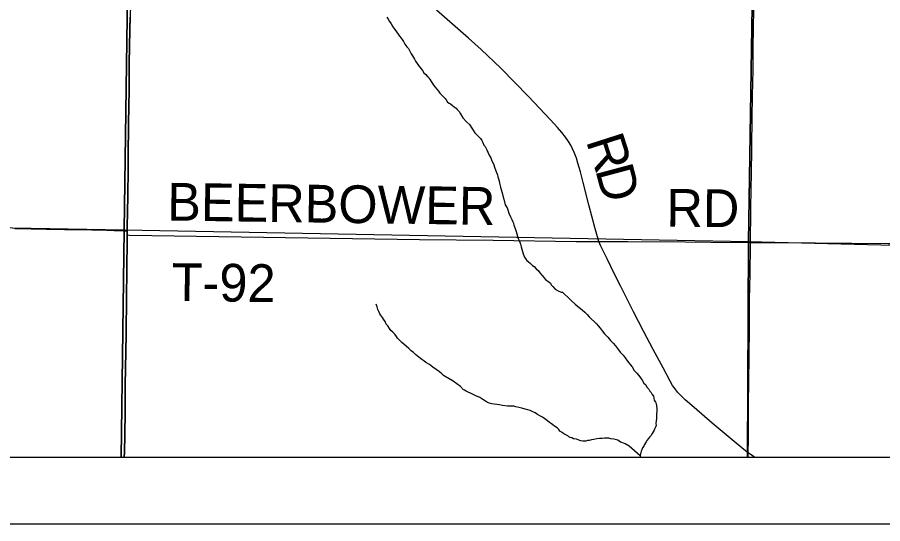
# Model space of a CAD drawing. Extents: x 0 to 34, y 0 to 22.
# Drawn here: x 6.454 to 7.757, y 14 to 14.762 of the extents above; entities that cross this region are included whole.
import ezdxf

# ---------------------------------------------------------------- set-up
doc = ezdxf.new("R2010")
doc.units = 0
for name, color, linetype in [('GM_X_County_Road', 7, 'Continuous'), ('GM_X_County_Road_Text', 7, 'Continuous'), ('GM_X_County_Text', 7, 'Continuous'), ('GM_X_Minor_River', 7, 'Continuous'), ('GM_X_Rail_Line_Text', 7, 'Continuous'), ('GM_X_Section', 7, 'Continuous'), ('GM_X_Township_Road', 7, 'Continuous'), ('GM_X_Township_Road_Text', 7, 'Continuous'), ('GM_X_US_Route', 7, 'Continuous'), ('SH_Cut_Line', 7, 'Continuous'), ('SH_Data', 7, 'Continuous')]:
    doc.layers.add(name, color=color, linetype=linetype)

msp = doc.modelspace()

# ---------------------------------------------------------------- linework, layer by layer
at = {"layer": 'GM_X_County_Road'}
for points in [[(7.3294, 14.425), (7.3236, 14.4459), (7.3145, 14.4802), (7.3057, 14.5135), (7.3017, 14.5298), (7.2981, 14.543), (7.2957, 14.5506), (7.2928, 14.5581), (7.29, 14.5643), (7.2872, 14.5698), (7.2837, 14.5756), (7.2792, 14.5822), (7.2739, 14.5891), (7.2675, 14.5966), (7.2569, 14.608), (7.2234, 14.6431), (7.182, 14.686), (7.1522, 14.7142), (7.1332, 14.7311), (7.0851, 14.7734)], [(7.5546, 14.1065), (7.5502, 14.1097), (7.5362, 14.1211), (7.5, 14.1516), (7.4731, 14.1747), (7.4596, 14.1866), (7.4533, 14.1926), (7.4482, 14.1982), (7.4442, 14.203), (7.4406, 14.2082), (7.4368, 14.2147), (7.4263, 14.2345), (7.4111, 14.2623), (7.3968, 14.2899), (7.3817, 14.3192), (7.3627, 14.357), (7.3525, 14.3769), (7.3424, 14.3976), (7.3326, 14.4177), (7.3294, 14.425)], [(7.564, 14.1), (7.5624, 14.101), (7.5546, 14.1065)]]:
    msp.add_lwpolyline(points, dxfattribs=at)
at = {"layer": 'GM_X_County_Text'}
for points in [[(2.1, 14.1), (6.615, 14.1), (6.6152, 14.1077), (6.6156, 14.1338), (6.6161, 14.1686), (6.6162, 14.1885), (6.6165, 14.2084), (6.6171, 14.2594), (6.6176, 14.2849), (6.6183, 14.3433), (6.6186, 14.3794), (6.6193, 14.4303), (6.6193, 14.4352), (6.6194, 14.4415), (6.6194, 14.4465), (6.6202, 14.4931), (6.6207, 14.5342), (6.621, 14.5565), (6.6216, 14.5988), (6.6221, 14.6324), (6.6222, 14.6492), (6.6222, 14.6647), (6.6226, 14.6952), (6.6231, 14.7176), (6.6236, 14.7449), (6.6241, 14.7629)], [(6.6241, 14.7629), (6.6236, 14.7449), (6.6231, 14.7176), (6.6226, 14.6952), (6.6222, 14.6647), (6.6222, 14.6492), (6.6221, 14.6324), (6.6216, 14.5988), (6.621, 14.5565), (6.6207, 14.5342), (6.6202, 14.4931), (6.6194, 14.4465), (6.6194, 14.4415), (6.6193, 14.4352), (6.6193, 14.4303), (6.6186, 14.3794), (6.6183, 14.3433), (6.6176, 14.2849), (6.6171, 14.2594), (6.6165, 14.2084), (6.6162, 14.1885), (6.6161, 14.1686), (6.6156, 14.1338), (6.6152, 14.1077), (6.615, 14.1), (8.9, 14.1)]]:
    msp.add_lwpolyline(points, dxfattribs=at)
at = {"layer": 'GM_X_Minor_River'}
for points in [[(7.0104, 14.7628), (7.0122, 14.7597), (7.0144, 14.7563), (7.0166, 14.7528), (7.0192, 14.7482), (7.0225, 14.7439), (7.0251, 14.7404), (7.0273, 14.7373), (7.0295, 14.7342), (7.0317, 14.7312), (7.0335, 14.7288), (7.0354, 14.7261), (7.0375, 14.7219), (7.0405, 14.718), (7.0427, 14.7153), (7.0438, 14.7134), (7.0456, 14.7107), (7.0471, 14.7076), (7.0489, 14.7045), (7.0507, 14.7018), (7.0522, 14.6995), (7.0537, 14.6964), (7.0558, 14.693), (7.0581, 14.6899), (7.0599, 14.6872), (7.0621, 14.6848), (7.064, 14.6825), (7.0661, 14.6786), (7.0691, 14.6763), (7.071, 14.674), (7.0728, 14.6724), (7.0743, 14.6705), (7.0754, 14.6682), (7.0769, 14.6659), (7.0791, 14.6628), (7.0805, 14.6601), (7.0879, 14.6511), (7.0901, 14.6484), (7.0931, 14.6453), (7.0949, 14.6434), (7.0979, 14.6403), (7.0997, 14.6383), (7.1019, 14.6349), (7.1042, 14.6333), (7.106, 14.6321), (7.1094, 14.6297), (7.1116, 14.6278), (7.1146, 14.6254), (7.1161, 14.6235), (7.1191, 14.6204), (7.1213, 14.6169), (7.1245, 14.6111), (7.1301, 14.6049), (7.1349, 14.601), (7.1382, 14.5956), (7.1426, 14.5883), (7.1485, 14.5828), (7.1511, 14.5801), (7.1533, 14.577), (7.1548, 14.5739), (7.1566, 14.5697), (7.1584, 14.5678), (7.1599, 14.5651), (7.161, 14.5628), (7.1624, 14.5593), (7.1642, 14.5547), (7.1668, 14.5508), (7.1686, 14.5462), (7.1707, 14.5416)], [(7.1707, 14.5416), (7.1729, 14.5351), (7.1754, 14.5286), (7.1768, 14.5255), (7.1775, 14.5225), (7.1782, 14.5194), (7.1792, 14.516), (7.1799, 14.5129), (7.1817, 14.5068), (7.1824, 14.503), (7.1838, 14.4984), (7.1848, 14.4934), (7.1866, 14.4884), (7.1887, 14.48), (7.1916, 14.4758), (7.1927, 14.4727), (7.1941, 14.4677), (7.1966, 14.462), (7.1984, 14.4581), (7.1995, 14.4554), (7.2009, 14.4527), (7.2016, 14.4493), (7.2034, 14.4443), (7.2048, 14.4401), (7.2062, 14.4363), (7.2083, 14.4294), (7.2098, 14.4263), (7.2105, 14.424), (7.2116, 14.4209), (7.2126, 14.4171), (7.2137, 14.4133), (7.2147, 14.4099), (7.2158, 14.4064), (7.2165, 14.4037), (7.2176, 14.4014), (7.2198, 14.3983), (7.2212, 14.3964), (7.2231, 14.3948), (7.2264, 14.3917), (7.2298, 14.389), (7.232, 14.3874), (7.2354, 14.3839), (7.238, 14.3812), (7.2409, 14.3777), (7.2442, 14.3738), (7.2494, 14.3676), (7.2546, 14.3637), (7.2569, 14.3621), (7.2579, 14.3594), (7.2605, 14.3571), (7.2639, 14.3532), (7.2684, 14.3504), (7.2729, 14.3488), (7.2748, 14.3484), (7.2781, 14.3449), (7.2826, 14.341), (7.2881, 14.3359), (7.2941, 14.3304), (7.2997, 14.3254), (7.3045, 14.3222), (7.3082, 14.3183), (7.312, 14.3152), (7.3149, 14.3117), (7.326, 14.3008), (7.3286, 14.2977), (7.3316, 14.2942), (7.3345, 14.2903), (7.3382, 14.286), (7.343, 14.2806), (7.3471, 14.2756), (7.3512, 14.2717), (7.3545, 14.2678), (7.3578, 14.2639), (7.3615, 14.2585), (7.3659, 14.2538), (7.3693, 14.2496), (7.3726, 14.2446), (7.3766, 14.2395), (7.3799, 14.236), (7.3825, 14.2306), (7.3869, 14.2267), (7.3895, 14.2233), (7.3921, 14.2194), (7.3947, 14.2159), (7.3972, 14.2117), (7.4002, 14.2089), (7.402, 14.2055), (7.4046, 14.2024), (7.4064, 14.1997), (7.4083, 14.1973), (7.4097, 14.1943), (7.4116, 14.1919), (7.4129, 14.1862), (7.4148, 14.1828), (7.4158, 14.1808), (7.4168, 14.1736), (7.4168, 14.1736), (7.4165, 14.161), (7.4161, 14.1584), (7.4156, 14.155), (7.4155, 14.1508)], [(7.0249, 14.2818), (7.0224, 14.2853), (7.0194, 14.2884), (7.0164, 14.2911), (7.0142, 14.2938), (7.0117, 14.2981), (7.0091, 14.3004), (7.0076, 14.3042), (7.0054, 14.3077), (7.0036, 14.3104), (7.0021, 14.3123), (7.001, 14.3143), (6.9999, 14.3162), (6.9985, 14.3197), (6.9967, 14.3227), (6.996, 14.3266), (6.9943, 14.3305)], [(7.3916, 14.102), (7.3752, 14.1168), (7.3693, 14.1204), (7.364, 14.1224), (7.3621, 14.1225), (7.358, 14.1256), (7.352, 14.1273), (7.3474, 14.1277), (7.3444, 14.1286), (7.341, 14.1287), (7.3379, 14.1287), (7.3345, 14.1284), (7.3307, 14.1285), (7.3265, 14.1279), (7.322, 14.1268), (7.3185, 14.1262), (7.3151, 14.1255), (7.3124, 14.1252), (7.3098, 14.1245), (7.3075, 14.1245), (7.3056, 14.1242), (7.3025, 14.1246), (7.3007, 14.1254), (7.2984, 14.1263), (7.2958, 14.1271), (7.2916, 14.1279), (7.289, 14.1291), (7.2863, 14.13), (7.2845, 14.1308), (7.2826, 14.1323), (7.2796, 14.1339), (7.277, 14.1355), (7.2744, 14.1371), (7.2706, 14.1395), (7.2692, 14.1418), (7.2666, 14.1445), (7.2628, 14.1469), (7.2602, 14.1488), (7.258, 14.1504), (7.2554, 14.1524), (7.252, 14.1551), (7.2483, 14.1579), (7.2445, 14.1602), (7.2408, 14.1626), (7.2374, 14.1646), (7.2337, 14.167), (7.2299, 14.1686), (7.2262, 14.1702), (7.2224, 14.1714), (7.2186, 14.1726), (7.2137, 14.1739), (7.2092, 14.1751), (7.2047, 14.176), (7.2013, 14.1768), (7.199, 14.1769), (7.1971, 14.1769), (7.1922, 14.1771), (7.1846, 14.178), (7.1801, 14.1789), (7.1759, 14.1794), (7.1717, 14.1798), (7.1683, 14.1807), (7.1649, 14.1815), (7.1619, 14.1827), (7.1589, 14.1847), (7.1548, 14.1871), (7.1503, 14.1899), (7.1443, 14.1923), (7.1402, 14.1943), (7.1361, 14.1963), (7.1327, 14.1979), (7.1297, 14.1995), (7.1274, 14.201), (7.1255, 14.2015), (7.1211, 14.2065), (7.1155, 14.2108), (7.1103, 14.2144), (7.0983, 14.2215), (7.0957, 14.2231), (7.0931, 14.2254), (7.0897, 14.2285), (7.0845, 14.2321), (7.0797, 14.2356), (7.0744, 14.2399), (7.0692, 14.2427), (7.0662, 14.2451), (7.0632, 14.247), (7.061, 14.2486), (7.0587, 14.2506), (7.0561, 14.2525), (7.0535, 14.2549), (7.0506, 14.2576), (7.0472, 14.2603), (7.0435, 14.2639), (7.0398, 14.2666), (7.0361, 14.2701), (7.0331, 14.2728), (7.0305, 14.2752), (7.0282, 14.2771), (7.0264, 14.2795), (7.0249, 14.2818)], [(7.4155, 14.1508), (7.4158, 14.1478), (7.4146, 14.1451), (7.4134, 14.1425), (7.4126, 14.1406), (7.4114, 14.1384), (7.4099, 14.1357), (7.4079, 14.1324), (7.4056, 14.1305), (7.4044, 14.1283), (7.402, 14.1253), (7.4008, 14.1234), (7.3997, 14.1216), (7.3985, 14.1193), (7.3973, 14.1167), (7.3953, 14.1141), (7.3941, 14.1114), (7.3933, 14.1092), (7.3921, 14.1054), (7.3916, 14.102), (7.3916, 14.1)]]:
    msp.add_lwpolyline(points, dxfattribs=at)
at = {"layer": 'GM_X_Rail_Line_Text'}
for points in [[(5.6017, 14.1), (6.6103, 14.1), (6.615, 14.4419), (5.6049, 14.4601)], [(6.6103, 14.1), (7.5533, 14.1), (7.5551, 14.4246), (6.615, 14.4419)], [(7.5533, 14.1), (8.5673, 14.1), (8.5711, 14.3987), (7.5551, 14.4246)]]:
    msp.add_lwpolyline(points, close=True, dxfattribs=at)
at = {"layer": 'GM_X_Section'}
for points in [[(5.6179, 15.4598), (6.6291, 15.4393), (6.615, 14.4419), (5.6049, 14.4601)], [(6.6291, 15.4393), (7.5704, 15.4246), (7.5551, 14.4246), (6.615, 14.4419)], [(7.5704, 15.4246), (8.5798, 15.3924), (8.5711, 14.3987), (7.5551, 14.4246)]]:
    msp.add_lwpolyline(points, close=True, dxfattribs=at)
at = {"layer": 'GM_X_Township_Road'}
msp.add_line((6.6196, 14.4347), (6.6196, 14.4409), dxfattribs=at)
for points in [[(6.6196, 14.4409), (6.6197, 14.4459), (6.6204, 14.4926), (6.6209, 14.5336), (6.6213, 14.556), (6.6218, 14.5983), (6.6223, 14.6318), (6.6224, 14.6486), (6.6225, 14.6642), (6.6228, 14.6946), (6.6233, 14.717), (6.6239, 14.7444), (6.6243, 14.7624), (6.6248, 14.7829)], [(6.45, 14.4447), (6.4749, 14.4441), (6.4979, 14.4437), (6.5252, 14.4432), (6.5663, 14.4426), (6.5881, 14.442), (6.5996, 14.4417), (6.6074, 14.4414), (6.6155, 14.441), (6.6196, 14.4409)], [(6.6153, 14.1), (6.6154, 14.1071), (6.6158, 14.1332), (6.6164, 14.168), (6.6164, 14.1879), (6.6167, 14.2078), (6.6174, 14.2588), (6.6178, 14.2843), (6.6185, 14.3427), (6.6189, 14.3788), (6.6195, 14.4298), (6.6196, 14.4347)], [(6.6196, 14.4347), (6.6229, 14.4346), (7.0593, 14.428), (7.1706, 14.4267), (7.2955, 14.4251), (7.3294, 14.425)], [(7.3294, 14.425), (7.3732, 14.425), (7.4596, 14.4245), (7.4988, 14.4241), (7.5579, 14.4236)], [(7.5579, 14.4236), (7.5777, 14.4234), (7.6555, 14.4229), (7.7649, 14.422), (7.8034, 14.4218), (7.855, 14.4217), (7.9638, 14.4213), (8.0266, 14.4208), (8.0709, 14.4198), (8.1099, 14.418), (8.1428, 14.4162), (8.2055, 14.413), (8.2595, 14.4104), (8.3396, 14.4062), (8.3849, 14.4038), (8.4923, 14.3981), (8.5184, 14.397), (8.56, 14.3953), (8.5855, 14.3943), (8.6116, 14.3936), (8.6408, 14.3933), (8.6681, 14.3928), (8.7023, 14.3925), (8.7401, 14.3919)]]:
    msp.add_lwpolyline(points, dxfattribs=at)
at = {"layer": 'GM_X_US_Route'}
msp.add_lwpolyline([(7.5546, 14.1), (7.5546, 14.1065), (7.5549, 14.1285), (7.5549, 14.1421), (7.5547, 14.1539), (7.5548, 14.1663), (7.5549, 14.1794), (7.5558, 14.2509), (7.5562, 14.2956), (7.5565, 14.3224), (7.5566, 14.3367), (7.557, 14.3578), (7.5572, 14.3752), (7.5578, 14.4206), (7.5579, 14.4236), (7.5584, 14.4716), (7.5591, 14.5069), (7.5593, 14.5249), (7.5606, 14.6107), (7.5609, 14.6449), (7.5617, 14.6828), (7.562, 14.7164), (7.5625, 14.7469), (7.5629, 14.773)], dxfattribs=at)
at = {"layer": 'SH_Cut_Line'}
msp.add_lwpolyline([(2.1, 16.5239), (2.1, 14.1), (8.9, 14.1), (8.9, 16.3981)], dxfattribs=at)
at = {"layer": 'SH_Data'}
for p, q in [((2.1, 14.1), (8.9, 14.1)), ((2, 14), (9, 14))]:
    msp.add_line(p, q, dxfattribs=at)

# ---------------------------------------------------------------- texts
at = {"layer": 'GM_X_County_Road_Text'}
for s, rotation, p in [('R', 287.7648, (7.3098, 14.5766)), ('D', 284.8951, (7.3239, 14.5329))]:
    msp.add_text(s, height=0.0568, rotation=rotation, dxfattribs=at).set_placement(p)
at = {"layer": 'GM_X_Township_Road_Text'}
for s, rotation, p in [('BEERBOWER', 359.2207, (6.6794, 14.4565)), ('RD', 359.5102, (7.4311, 14.4473)), ('T-92', 359.2931, (6.6862, 14.3355))]:
    msp.add_text(s, height=0.05682, rotation=rotation, dxfattribs=at).set_placement(p)

doc.saveas('drawing.dxf')
